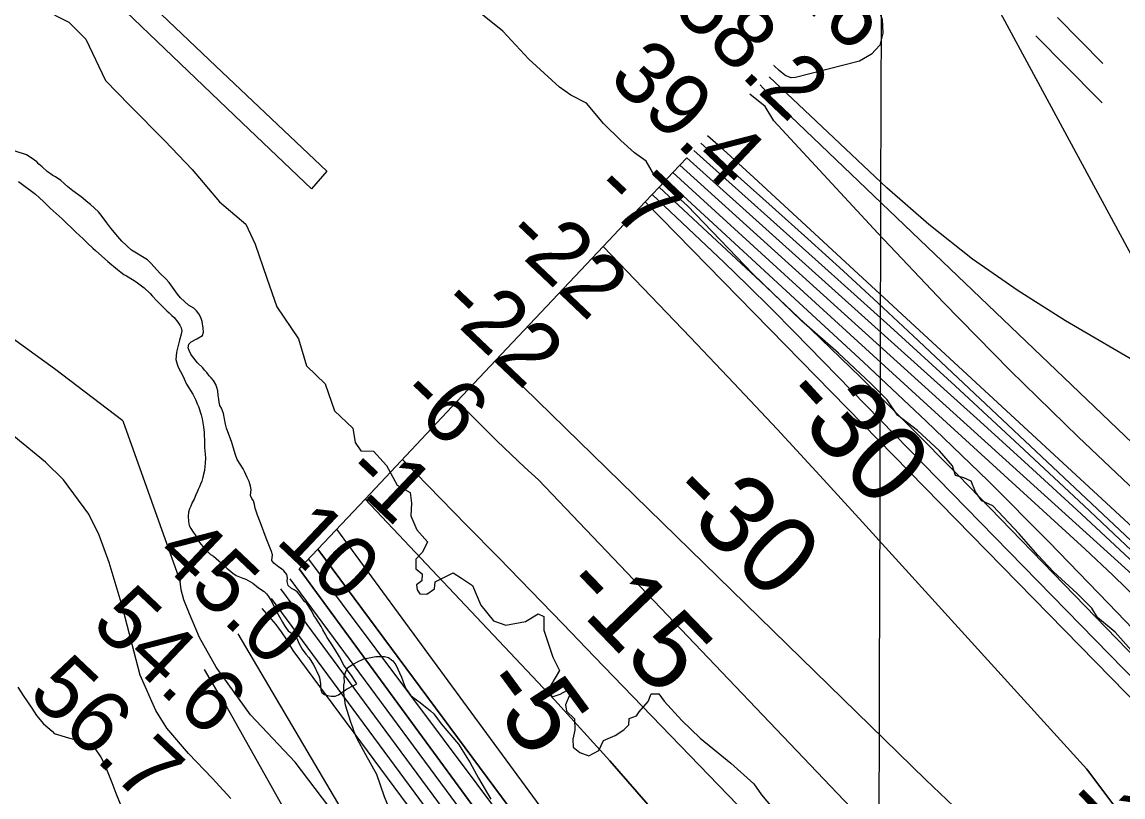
# Model space of a CAD drawing. Extents: x 3146026 to 3183936, y 897894 to 923344.
# Drawn here: x 3175467 to 3176638, y 908497 to 909321 of the extents above; entities that cross this region are included whole.
import ezdxf

# ---------------------------------------------------------------- set-up
doc = ezdxf.new("R2010")
doc.units = 0
for name, color, linetype in [('V-GRID-MAJR', 7, 'Continuous'), ('V-LEVE-TOET', 7, 'Continuous'), ('V-RIVR-EDGE', 7, 'Continuous'), ('V-RIVR-JETY', 7, 'Continuous'), ('V-RIVR-RANG', 7, 'Continuous'), ('V-ROAD-CNTR', 7, 'Continuous'), ('V-SITE-VEGE', 7, 'Continuous'), ('V-TOPO-DPTH', 7, 'Continuous'), ('V-TOPO-MAJR', 7, 'Continuous'), ('V-TOPO-MINR', 7, 'Continuous'), ('V-TOPO-MINR-IDEN', 7, 'Continuous'), ('V-TOPO-WATR', 7, 'Continuous'), ('V-TRAN-LOCK', 7, 'Continuous')]:
    doc.layers.add(name, color=color, linetype=linetype)

msp = doc.modelspace()

# ---------------------------------------------------------------- linework, layer by layer
at = {"layer": 'V-GRID-MAJR'}
msp.add_spline([(3176363.2, 903291), (3176380.9, 909351.9), (3176398.5, 915414.8), (3176416.1, 921477.7), (3176416.1, 921479.6)], degree=3, dxfattribs=at)
at = {"layer": 'V-LEVE-TOET'}
msp.add_line((3175574.2, 908896.6), (3175635, 908725.8), dxfattribs=at)
for points in [[(3175574.2, 908896.6), (3175501.2, 908951.9), (3175377.8, 909041.2), (3175279.2, 909112.8), (3175164.7, 909201.7), (3175167, 909230)], [(3175688.9, 908495.2), (3175668.9, 908516.7), (3175643.9, 908542.8), (3175620.9, 908569.9), (3175609.2, 908588.7), (3175592.6, 908626.1), (3175583.8, 908658.7), (3175573.5, 908699.8), (3175559.6, 908746), (3175549, 908775.2), (3175537.7, 908797.4), (3175511, 908833.9), (3175491.7, 908852.6), (3175458.2, 908880.3)], [(3176295.7, 907744), (3176244.4, 907830.1), (3176156.6, 907973.9), (3176064.8, 908114.5), (3175959, 908265.4), (3175843.6, 908420.3), (3175757.2, 908533.7), (3175709.8, 908584.1), (3175673.3, 908634.6), (3175655.7, 908666.2), (3175644.9, 908691.4), (3175638.8, 908706.4), (3175636.1, 908717), (3175635, 908725.8)]]:
    msp.add_lwpolyline(points, dxfattribs=at)
at = {"layer": 'V-RIVR-EDGE'}
for points in [[(3175454.2, 909382.8), (3175470.4, 909367), (3175487.9, 909335), (3175516.5, 909320.6), (3175534.6, 909302.5), (3175555.5, 909258.6), (3175581.1, 909232.3), (3175618.7, 909194.5), (3175647.7, 909163.9), (3175676.7, 909129.5), (3175704.8, 909105.6), (3175714.8, 909084.6), (3175727.1, 909048.3), (3175738, 909017.8), (3175760.8, 908983.8), (3175769.3, 908955.2), (3175789.3, 908936.1), (3175799.2, 908907.4), (3175818.7, 908888.8), (3175821.1, 908873.5)], [(3176669.3, 908627.4), (3176629.3, 908671.9), (3176610.8, 908687.6), (3176604.8, 908697.3), (3176589.2, 908713.1), (3176563.8, 908736.2), (3176547.2, 908753.8), (3176527.4, 908776.5), (3176499.3, 908806.1), (3176487.8, 908811.7), (3176480.9, 908821), (3176476.3, 908832.5), (3176468.5, 908836.2), (3176459.7, 908838.6), (3176456.5, 908848.7), (3176442.7, 908864.9), (3176419.2, 908886.2), (3176398, 908902.5), (3176386.9, 908919.1), (3176369.4, 908936.2), (3176335.3, 908968.7), (3176295.7, 909002.9), (3176244.1, 909052.9), (3176174.5, 909125.2), (3176139.9, 909156.7), (3176130.7, 909172.8), (3176118.3, 909181.7), (3176103.6, 909194.6), (3176085.1, 909212.7), (3176067.2, 909234.4), (3176050.6, 909242.8), (3176038.6, 909251.6), (3176005.8, 909281.2), (3175978.2, 909310.9), (3175937.2, 909344.2)], [(3175821.1, 908873.5), (3175827.3, 908864.9), (3175840.6, 908864.4), (3175854.4, 908849.1), (3175865.8, 908828.1), (3175879.6, 908820.5), (3175881, 908809), (3175880.5, 908795.7), (3175886.7, 908780.9), (3175898.1, 908768), (3175892.8, 908757), (3175885.6, 908749.4), (3175885.6, 908739.4), (3175892.3, 908734.1), (3175892.2, 908726.5), (3175886.5, 908722.2), (3175887, 908717), (3175889.8, 908712.7), (3175897.5, 908712.2), (3175905.6, 908717.9), (3175906.1, 908725.5), (3175925.2, 908735), (3175934.2, 908729.2), (3175946.1, 908721.6), (3175954.7, 908700.6), (3175968.4, 908683.9), (3175981.3, 908679.5), (3176002.3, 908683.3), (3176015.7, 908691.4), (3176021.9, 908688.5), (3176021.8, 908674.2), (3176031.3, 908645.5), (3176038.4, 908631.2), (3176029.3, 908615.5), (3176029.3, 908606), (3176030.7, 908603.1), (3176039.3, 908605.9), (3176050.3, 908612.1), (3176050.3, 908607.3), (3176045, 908594.5), (3176045.9, 908587.8), (3176054.5, 908579.7), (3176054.9, 908567.8), (3176052.5, 908558.2), (3176053, 908549.6), (3176060.1, 908543.9), (3176069.7, 908540.5), (3176080.2, 908546.2), (3176085.4, 908556.7), (3176097.8, 908561.9), (3176106.9, 908568.1), (3176112.2, 908573.3), (3176112.7, 908580), (3176120.3, 908582.9), (3176123.2, 908587.1), (3176132.7, 908598.1), (3176136.1, 908606.2), (3176144.2, 908606.2), (3176149.9, 908598.5), (3176168.5, 908578), (3176188, 908559.3), (3176220.8, 908532.5), (3176245.1, 908510.5), (3176253.2, 908499.1), (3176274.1, 908474.2)]]:
    msp.add_lwpolyline(points, dxfattribs=at)
at = {"layer": 'V-RIVR-JETY'}
for points in [[(3175471.5, 909179.4), (3175459.7, 909183.5)], [(3175529.7, 909134.7), (3175520.9, 909141.2), (3175515.6, 909145.6), (3175508, 909152.2), (3175502.3, 909156), (3175499.5, 909157.6), (3175493.7, 909161.9), (3175488.2, 909166.9), (3175484.8, 909169.7), (3175482.4, 909172.1), (3175476.4, 909176.3), (3175471.5, 909179.4)], [(3175463.1, 909151.1), (3175481, 909137.5), (3175489.8, 909129.8), (3175496.9, 909122.8), (3175509.4, 909111.6), (3175524.1, 909097.3), (3175531.8, 909090.1), (3175536.4, 909085.5), (3175542, 909080.2), (3175544.9, 909077.8), (3175558, 909066.2), (3175568.4, 909057.5), (3175572, 909054.9), (3175575.1, 909052.1), (3175578.1, 909050.7), (3175584.3, 909047.1), (3175588.1, 909044.3), (3175591.2, 909042.2), (3175596.6, 909038), (3175603.2, 909032), (3175605.3, 909029.4), (3175610.5, 909023.8), (3175615.7, 909018.6), (3175618, 909016.6), (3175621, 909013.5), (3175623.4, 909011.5), (3175626.2, 909008.7), (3175628.8, 909006.5), (3175632.5, 909001.7), (3175634.7, 908998.5), (3175636.1, 908995.5), (3175636.9, 908992.5), (3175636.2, 908988.9), (3175634.2, 908982.3), (3175631.8, 908972.6), (3175631.2, 908969.6), (3175630.7, 908965.8), (3175630.5, 908961.8), (3175631.9, 908956.8), (3175632.9, 908953.6), (3175637.8, 908944.6), (3175641.9, 908935.8), (3175648.5, 908925), (3175651.6, 908918.6), (3175653.2, 908914.8), (3175654.4, 908912), (3175657.3, 908903), (3175658.5, 908898.6), (3175659.8, 908890.4), (3175660.4, 908884.2), (3175660.9, 908872.8), (3175660.9, 908868.2), (3175661.7, 908861.2), (3175661.9, 908857.1), (3175661.6, 908851.5), (3175661.4, 908848.1), (3175660.8, 908843.9), (3175659.8, 908840.1), (3175659.1, 908836.5), (3175658.8, 908835.3), (3175658.1, 908832.5), (3175656.7, 908829.3), (3175655.5, 908826.4), (3175654.3, 908823.8), (3175653.3, 908821.8), (3175651.7, 908817.8), (3175649.8, 908813.4), (3175647.8, 908809.8), (3175646.2, 908805.8), (3175645, 908803.1), (3175643.8, 908799.5), (3175643.4, 908795.3), (3175643.9, 908789.7), (3175644.7, 908785.5), (3175646.3, 908782.3)], [(3175822.8, 908617), (3175817.8, 908624.8), (3175809.1, 908637), (3175804.4, 908645.6), (3175799.4, 908654), (3175796.3, 908658.7), (3175791.5, 908666.1), (3175789.3, 908670.1), (3175786.6, 908674.5), (3175784.8, 908678.1), (3175779.3, 908686.9), (3175777.3, 908689.7), (3175774.9, 908694.3), (3175769.6, 908702.3), (3175767.4, 908704.7), (3175762, 908711.9), (3175759.5, 908714.9), (3175756.3, 908717.1), (3175753.3, 908718.2), (3175749.9, 908721.4), (3175748.9, 908725.8), (3175749.2, 908729.6), (3175748.4, 908733.2), (3175745.4, 908737), (3175742.8, 908739.4), (3175740, 908741), (3175734.7, 908745.4), (3175732.5, 908748), (3175733.3, 908754), (3175732.2, 908757.6), (3175726.4, 908772), (3175720.5, 908788.2), (3175717.2, 908796.4), (3175714.8, 908803.6), (3175714.1, 908807.8), (3175712.9, 908811.6), (3175711.1, 908814.2), (3175709.9, 908817.4), (3175710, 908820.6), (3175710.4, 908823.8), (3175709.8, 908827.2), (3175708.4, 908832), (3175706.2, 908836.4), (3175703.5, 908842.6), (3175701.9, 908845.6), (3175695.8, 908855.6), (3175693.8, 908860.6), (3175692.4, 908865), (3175690.1, 908873.6), (3175684.4, 908889), (3175683.4, 908893), (3175681.1, 908904.4), (3175680.1, 908907.4), (3175678.9, 908910.2), (3175677.1, 908912.8), (3175676.4, 908916.4), (3175676.2, 908919.8), (3175675.4, 908923.8), (3175675.2, 908928.5), (3175673.9, 908932.1), (3175672.9, 908935.3), (3175670.3, 908939.4), (3175667.9, 908942.2), (3175665.7, 908944.4), (3175663.2, 908948), (3175661, 908950.4), (3175659, 908953), (3175653.6, 908958.2), (3175648.3, 908965), (3175646.5, 908967.6), (3175644.7, 908971.4), (3175643.6, 908974.4), (3175644.4, 908978.2), (3175646.8, 908980.8), (3175652.8, 908983.8), (3175658.8, 908987.5), (3175660, 908991.1), (3175659.6, 908995.3), (3175658.5, 909002.3), (3175656.9, 909006.5), (3175654.9, 909010.5), (3175652.4, 909013.7), (3175649.4, 909016.3), (3175644, 909019.7), (3175635.3, 909027.6), (3175632.1, 909031.4), (3175623.2, 909043.8), (3175619.6, 909047.8), (3175613.5, 909053.8), (3175604.3, 909064), (3175600.4, 909067.7), (3175583.1, 909078.1), (3175572.9, 909087.8), (3175568.8, 909092.8), (3175561.2, 909101.4), (3175557.1, 909107.2), (3175550.9, 909115.2), (3175548, 909118.8), (3175539.8, 909126.7), (3175536.8, 909128.7), (3175529.7, 909134.7)], [(3175646.3, 908782.3), (3175648.8, 908778.1), (3175651, 908775.3), (3175653.6, 908771.1), (3175655, 908768.3), (3175657, 908765.5), (3175659.5, 908762.5), (3175664.9, 908756.9), (3175667.3, 908754.6), (3175670.3, 908752.8), (3175676, 908747.6), (3175678.6, 908745.6), (3175681, 908743.4), (3175684.8, 908739.8), (3175690.9, 908734.6), (3175694.7, 908732.3), (3175701.5, 908729.5), (3175704.8, 908728.3), (3175712.4, 908723.9), (3175718.4, 908719), (3175724.5, 908715.2), (3175726.7, 908712.8), (3175729.1, 908709.8), (3175731.5, 908706), (3175733.4, 908702), (3175737.6, 908694), (3175743.9, 908682.4), (3175746.3, 908678.4), (3175750, 908673.4), (3175756.8, 908668.5), (3175759, 908665.7), (3175761.3, 908660.3), (3175764.9, 908653.7), (3175768.7, 908648.7), (3175771.8, 908644.9), (3175774, 908641.7), (3175776.8, 908637.1), (3175779, 908633.3), (3175780.1, 908630.5), (3175782.1, 908626.7), (3175783.3, 908623.5), (3175784.1, 908617.3), (3175784.2, 908614.1), (3175784.6, 908610.5), (3175785.8, 908607.7), (3175788.4, 908605.5), (3175791.6, 908604.5), (3175795.6, 908603.7), (3175799.7, 908603.8), (3175803.5, 908605.4), (3175811.8, 908611.3), (3175814.6, 908612.7), (3175817.4, 908614.3), (3175820.4, 908615.7), (3175822.8, 908617)]]:
    msp.add_lwpolyline(points, dxfattribs=at)
at = {"layer": 'V-ROAD-CNTR'}
for points in [[(3176568.2, 909325.4), (3176616.2, 909276.7)], [(3176545.2, 909305.9), (3176610.5, 909239.7), (3176615.5, 909234.8)]]:
    msp.add_lwpolyline(points, dxfattribs=at)
at = {"layer": 'V-SITE-VEGE'}
for p, q in [((3175834.4, 908644.2), (3175843.2, 908646)), ((3175843.2, 908646), (3175852.4, 908646)), ((3175852.4, 908646), (3175856.6, 908645)), ((3175856.6, 908645), (3175861.2, 908641.3)), ((3175810.7, 908629.1), (3175813.5, 908634.2)), ((3175813.5, 908634.2), (3175819.1, 908637.8)), ((3175819.1, 908637.8), (3175824.2, 908640.6)), ((3175824.2, 908640.6), (3175828.8, 908642.9)), ((3175828.8, 908642.9), (3175831.1, 908643.8)), ((3175831.1, 908643.8), (3175834.4, 908644.2)), ((3175861.2, 908641.3), (3175864.4, 908637.1)), ((3175864.4, 908637.1), (3175870.4, 908624.1)), ((3175809.3, 908624.5), (3175810.7, 908629.1)), ((3175809.7, 908618.9), (3175809.3, 908624.5)), ((3175870.4, 908624.1), (3175873.5, 908615.3)), ((3175462.5, 908613.4), (3175468, 908604.6)), ((3175809.2, 908615.7), (3175809.7, 908618.9)), ((3175809.2, 908607.3), (3175809.2, 908615.7)), ((3175873.5, 908615.3), (3175875.8, 908611.1)), ((3175875.8, 908611.1), (3175880, 908605.1)), ((3175468, 908604.6), (3175477.2, 908591.1)), ((3175810.9, 908594.4), (3175809.2, 908607.3)), ((3175880, 908605.1), (3175882.3, 908602.8)), ((3175882.3, 908602.8), (3175890.1, 908597.2)), ((3175477.2, 908591.1), (3175482.2, 908583.2)), ((3175816.4, 908576.3), (3175810.9, 908594.4)), ((3175890.1, 908597.2), (3175901.2, 908588.3)), ((3175901.2, 908588.3), (3175904.9, 908585)), ((3175482.2, 908583.2), (3175489.6, 908574.4)), ((3175818.7, 908570.7), (3175816.4, 908576.3)), ((3175904.9, 908585), (3175912.7, 908574.3)), ((3175489.6, 908574.4), (3175498.8, 908566.5)), ((3175498.8, 908566.5), (3175501.1, 908564.1)), ((3175501.1, 908564.1), (3175516.3, 908559.4)), ((3175820, 908566.1), (3175818.7, 908570.7)), ((3175822.8, 908559.1), (3175820, 908566.1)), ((3175912.7, 908574.3), (3175931.1, 908553)), ((3175516.3, 908559.4), (3175525.6, 908557.1)), ((3175525.6, 908557.1), (3175531.6, 908555.2)), ((3175531.6, 908555.2), (3175544.5, 908547.7)), ((3175832.4, 908541.5), (3175822.8, 908559.1)), ((3175931.1, 908553), (3175943.5, 908533)), ((3175544.5, 908547.7), (3175550.5, 908538.9)), ((3175844.3, 908520.6), (3175832.4, 908541.5)), ((3175550.5, 908538.9), (3175554.6, 908531.4)), ((3175554.6, 908531.4), (3175560.1, 908517.5)), ((3175943.5, 908533), (3175952.2, 908516.7)), ((3175560.1, 908517.5), (3175562.4, 908512)), ((3175852.5, 908496.9), (3175844.3, 908520.6)), ((3175952.2, 908516.7), (3175965.5, 908494.4)), ((3175562.4, 908512), (3175566.5, 908500.8)), ((3175566.5, 908500.8), (3175580.6, 908467)), ((3175858, 908483), (3175852.5, 908496.9))]:
    msp.add_line(p, q, dxfattribs=at)
at = {"layer": 'V-TOPO-DPTH'}
msp.add_line((3176129.5, 909129.4), (3176144.3, 909145), dxfattribs=at)
for points in [[(3176159.1, 909160.7), (3176173.8, 909176.3), (3176485.7, 908895.8), (3176537.2, 908849.1), (3176588.5, 908802.1), (3176639.5, 908754.8), (3176690.2, 908707.2), (3176753.3, 908647.4)], [(3176665, 908630), (3176462.5, 908838.7), (3176410.8, 908891.1), (3176358.6, 908943), (3176305.6, 908994.1), (3176252.1, 909044.7), (3176144.3, 909145), (3176159.1, 909160.7)], [(3176722.2, 908634.2), (3176711.4, 908646.1), (3176683.9, 908675.5), (3176655.8, 908704.4), (3176627, 908732.5), (3176597.6, 908760.1), (3176159.1, 909160.7)], [(3176159.1, 909160.7), (3176597.6, 908760.1), (3176627, 908732.5), (3176655.8, 908704.4), (3176683.9, 908675.5), (3176711.4, 908646.1), (3176722.2, 908634.2)], [(3176144.3, 909145), (3176252.1, 909044.7), (3176305.6, 908994.1), (3176358.6, 908943), (3176410.8, 908891.1), (3176462.5, 908838.7), (3176665, 908630)], [(3176129.5, 909129.4), (3176085, 909082.1), (3176177.8, 908985.3), (3176224, 908936.6), (3176269.9, 908887.8), (3176315.5, 908838.5), (3176360.7, 908789), (3176599.2, 908526.2)], [(3176657.8, 908589.9), (3176129.8, 909129.1), (3176129.5, 909129.4)], [(3176657.8, 908589.9), (3176129.8, 909129.1), (3176129.5, 909129.4)], [(3176486.6, 908459.6), (3176472.8, 908472.3), (3176450.4, 908493.5), (3176428.2, 908514.9), (3175970.8, 908961.1), (3176085, 909082.1)], [(3176085, 909082.1), (3176177.8, 908985.3), (3176224, 908936.6), (3176269.9, 908887.8), (3176315.5, 908838.5), (3176360.7, 908789), (3176599.2, 908526.2)], [(3175929.6, 908917.4), (3175970.8, 908961.1), (3176428.2, 908514.9), (3176450.4, 908493.5), (3176472.8, 908472.3), (3176486.6, 908459.6)], [(3176320.9, 908224.3), (3176204.4, 908401.4), (3176149.4, 908469.3), (3176092.1, 908535.2), (3176033.2, 908599.8), (3175831.6, 908813.4), (3175929.6, 908917.4)], [(3175929.6, 908917.4), (3175958, 908889.1), (3175972.3, 908875.1), (3175986.7, 908861.2), (3176001.4, 908847.5), (3176016.1, 908833.9), (3176456.9, 908371.8)], [(3176456.9, 908371.8), (3176016.1, 908833.9), (3176001.4, 908847.5), (3175986.7, 908861.2), (3175972.3, 908875.1), (3175958, 908889.1), (3175929.6, 908917.4)], [(3175781.4, 908760.3), (3175831.6, 908813.4), (3176033.2, 908599.8), (3176092.1, 908535.2), (3176149.4, 908469.3), (3176204.4, 908401.4), (3176320.9, 908224.3)], [(3176215.7, 908110.2), (3176178.7, 908175.1), (3176156.7, 908201.7), (3176140.6, 908222.3), (3175761.5, 908739.2), (3175781.4, 908760.3)], [(3176242.2, 908138.9), (3175781.4, 908760.3)], [(3175781.4, 908760.3), (3176242.2, 908138.9)], [(3176599.2, 908526.2), (3176649.2, 908459.5), (3177055, 907876.8), (3177060, 907869.9), (3177064.8, 907862.8), (3177069.1, 907855.4), (3177073.1, 907847.9), (3177076.1, 907841.8), (3177078.2, 907837.1), (3177080.1, 907832.2), (3177081.5, 907827.3), (3177082.7, 907822.3), (3177090.6, 907783.5), (3177095, 907759), (3177206.2, 906913.7)], [(3176599.2, 908526.2), (3176649.2, 908459.5), (3177055, 907876.8), (3177060, 907869.9), (3177064.8, 907862.8), (3177069.1, 907855.4), (3177073.1, 907847.9), (3177076.1, 907841.8), (3177078.2, 907837.1), (3177080.1, 907832.2), (3177081.5, 907827.3), (3177082.7, 907822.3), (3177090.6, 907783.5), (3177095, 907759), (3177206.2, 906913.7)]]:
    msp.add_lwpolyline(points, dxfattribs=at)
at = {"layer": 'V-TOPO-MAJR'}
for points in [[(3176782.3, 908659.6), (3176245.3, 909155.5), (3176237.1, 909163), (3176229, 909170.4), (3176220.8, 909177.8), (3176212.5, 909185.2), (3176196, 909199.8)], [(3175731.7, 908707.6), (3176146.2, 908146.3), (3176191.4, 908083.8)]]:
    msp.add_lwpolyline(points, dxfattribs=at)
at = {"layer": 'V-TOPO-MINR'}
for points in [[(3176402.1, 909424.5), (3176402.9, 909420.6), (3176403.1, 909420.1), (3176403.8, 909419.3), (3176404.3, 909419), (3176438.9, 909405.4), (3176455.3, 909396.7), (3176470.1, 909386.2), (3176482.3, 909372.8), (3176492.9, 909357.5), (3176688.9, 908994.4), (3176691.9, 908985.8), (3176693.2, 908977.2), (3176691.9, 908968.6), (3176688.9, 908960), (3176683.4, 908954.2), (3176677.3, 908950.7)], [(3176360.1, 909368.7), (3176362.5, 909366.7), (3176363.9, 909365), (3176366.5, 909361.6), (3176368.9, 909357.9), (3176370.8, 909354), (3176372.4, 909350), (3176381.5, 909323.3), (3176382.2, 909308.7), (3176379.2, 909296.1), (3176370.3, 909286.6), (3176357.6, 909279.2), (3176289.4, 909261.7), (3176284.7, 909261.5)], [(3176284.7, 909261.5), (3176280.2, 909263), (3176278.1, 909264.3), (3176276, 909265.8), (3176274.1, 909267.3), (3176272.2, 909269), (3176266.8, 909274), (3176266.5, 909274.4), (3176266.6, 909274.9)], [(3176677.3, 908950.7), (3176670.3, 908950.6), (3176662.6, 908952.6), (3176576.7, 909003.1), (3176526.4, 909034.8), (3176477.7, 909068.6), (3176431.3, 909105.5), (3176386.5, 909144.5), (3176261.6, 909262.6)], [(3176803.3, 908680.5), (3176664.2, 908809.3), (3176590.5, 908879.1), (3176517.9, 908950.1), (3176446.9, 909022.6), (3176377, 909096.3), (3176266.5, 909215.6), (3176257.1, 909231), (3176240.8, 909243.9)], [(3177042.4, 908793.2), (3176992.9, 908737.7), (3176949.8, 908695.1), (3176947.1, 908693), (3176944.3, 908691.3), (3176941.1, 908690.2), (3176937.8, 908689.6), (3176934.2, 908689.2), (3176930.7, 908688.8), (3176927.2, 908688.3), (3176923.7, 908687.7), (3176863.8, 908677.4), (3176860.7, 908677.3), (3176857.7, 908677.5), (3176854.8, 908678.4), (3176851.9, 908679.7), (3176849.2, 908681.4), (3176846.6, 908683.3), (3176844.1, 908685.3), (3176841.7, 908687.4), (3176267.7, 909236.2), (3176251.7, 909253.8)], [(3176761.3, 908650.6), (3176596, 908806.5), (3176527.7, 908870.3), (3176459.1, 908933.9), (3176390, 908996.8), (3176320.6, 909059.5), (3176181.2, 909184.2)], [(3176764.9, 908657.9), (3176414.7, 908987), (3176377.5, 909021.6), (3176340.1, 909056.1), (3176302.4, 909090.3), (3176264.6, 909124.3), (3176188.6, 909192)], [(3176753.3, 908647.4), (3176690.2, 908707.2), (3176639.5, 908754.8), (3176588.5, 908802.1), (3176537.2, 908849.1), (3176485.7, 908895.8), (3176173.8, 909176.3)], [(3176750.2, 908639.5), (3176744.7, 908644.8), (3176731, 908657.6), (3176717.2, 908670.3), (3176703.3, 908682.9), (3176166.5, 909168.5)], [(3176691.4, 908630.4), (3176622.5, 908702.5), (3176558.8, 908768.1), (3176494.2, 908832.9), (3176428.3, 908896.4), (3176361.7, 908959), (3176151.7, 909152.8)], [(3176668.7, 908601.7), (3176288.5, 908990.8), (3176263.8, 909015.8), (3176238.9, 909040.5), (3176213.6, 909065), (3176188.2, 909089.1), (3176136.9, 909137.2)], [(3176665, 908630), (3176462.5, 908838.7), (3176410.8, 908891.1), (3176358.6, 908943), (3176305.6, 908994.1), (3176252.1, 909044.7), (3176144.3, 909145)], [(3176657.8, 908589.9), (3176129.8, 909129.1), (3176129.5, 909129.4)], [(3176599.2, 908526.2), (3176360.7, 908789), (3176315.5, 908838.5), (3176269.9, 908887.8), (3176224, 908936.6), (3176177.8, 908985.3), (3176085, 909082.1)], [(3175970.8, 908961.1), (3176428.2, 908514.9), (3176450.4, 908493.5), (3176472.8, 908472.3), (3176486.6, 908459.6)], [(3175929.6, 908917.4), (3175958, 908889.1), (3175972.3, 908875.1), (3175986.7, 908861.2), (3176001.4, 908847.5), (3176016.1, 908833.9), (3176456.9, 908371.8)], [(3175871.4, 908855.6), (3175939.7, 908785.8), (3175973.8, 908750.9), (3176007.9, 908715.9), (3176041.9, 908680.9), (3176075.8, 908645.8), (3176400.1, 908310.2)], [(3175831.6, 908813.4), (3176033.2, 908599.8), (3176092.1, 908535.2), (3176149.4, 908469.3), (3176204.4, 908401.4), (3176320.9, 908224.3)], [(3175801.4, 908781.4), (3176259.3, 908157.5)], [(3175761.5, 908739.2), (3176140.6, 908222.3), (3176156.7, 908201.7), (3176178.7, 908175.1), (3176215.7, 908110.2)], [(3175771.5, 908749.7), (3176164.3, 908224.7), (3176172.9, 908210.7), (3176182, 908197), (3176188.6, 908187.9), (3176227.8, 908123.3)], [(3175751.6, 908728.7), (3176169.4, 908163.2), (3176205.4, 908099)], [(3175741.6, 908718.1), (3176159.7, 908152.1), (3176197.1, 908090)], [(3175721.8, 908697), (3175736.6, 908679.9), (3175739.2, 908676.7), (3175741.7, 908673.4), (3175744, 908670), (3175746.2, 908666.5), (3175748.4, 908663), (3175750.5, 908659.4), (3175752.7, 908655.9), (3175754.8, 908652.4), (3176140.8, 908131.3), (3176184.8, 908076.6)], [(3175696.2, 908670), (3176100.4, 907985)], [(3175660.5, 908632.1), (3175676.2, 908605.8), (3175680.4, 908598.9), (3175684.6, 908592.2), (3176055.5, 907932)], [(3177206.2, 906913.7), (3177095, 907759), (3177090.6, 907783.5), (3177082.7, 907822.3), (3177081.5, 907827.3), (3177080.1, 907832.2), (3177078.2, 907837.1), (3177076.1, 907841.8), (3177073.1, 907847.9), (3177069.1, 907855.4), (3177064.8, 907862.8), (3177060, 907869.9), (3177055, 907876.8), (3176649.2, 908459.5), (3176599.2, 908526.2)]]:
    msp.add_lwpolyline(points, dxfattribs=at)
at = {"layer": 'V-TOPO-WATR'}
for points in [[(3176722.2, 908634.2), (3176711.4, 908646.1), (3176683.9, 908675.5), (3176655.8, 908704.4), (3176627, 908732.5), (3176597.6, 908760.1), (3176159.1, 909160.7)], [(3175781.4, 908760.3), (3176242.2, 908138.9)]]:
    msp.add_lwpolyline(points, dxfattribs=at)
at = {"layer": 'V-TRAN-LOCK'}
msp.add_lwpolyline([(3175321.3, 909607.1), (3175346.2, 909585.4), (3175432, 909504.2), (3175550.2, 909390.9), (3175673, 909273.8), (3175791.1, 909162.2), (3175774.7, 909143.2), (3175700.9, 909213.4), (3175494.9, 909410.9), (3175395.1, 909506), (3175358.3, 909540.6), (3175353, 909535.2), (3175330.6, 909556.1), (3175325.9, 909550.8)], dxfattribs=at)

# ---------------------------------------------------------------- texts
at = {"layer": 'V-RIVR-RANG'}
for s, rotation, p in [('59.6', 316.5383, (3176224.8, 909406.2)), ('58.2', 316.5383, (3176157.5, 909332.2)), ('39.4', 316.5383, (3176088.9, 909259.4)), ('-7', 316.5383, (3176070.7, 909138.9)), ('-22', 316.5383, (3175976.8, 909090.2)), ('-22', 316.5383, (3175908.2, 909017.4)), ('-6', 316.5383, (3175864.8, 908920.7)), ('-1', 316.5383, (3175806.4, 908838.3)), ('10', 316.5383, (3175735.1, 908768.1)), ('45.0', 316.5383, (3175606.5, 908752.2)), ('54.6', 316.5383, (3175538.7, 908678.7)), ('56.7', 316.5383, (3175471.4, 908604.7)), ('-19', 314.2283, (3176571.8, 908487))]:
    msp.add_text(s, height=67, rotation=rotation, dxfattribs=at).set_placement(p)
at = {"layer": 'V-TOPO-MINR-IDEN'}
for s, rotation, p in [('-30', 312.4516, (3176269.9, 908919.1)), ('-30', 315.7119, (3176150.3, 908815)), ('-15', 314.0095, (3176036.7, 908716.2)), ('-5', 306.2749, (3175950.1, 908613.8))]:
    msp.add_text(s, height=83, rotation=rotation, dxfattribs=at).set_placement(p)

doc.saveas('drawing.dxf')
